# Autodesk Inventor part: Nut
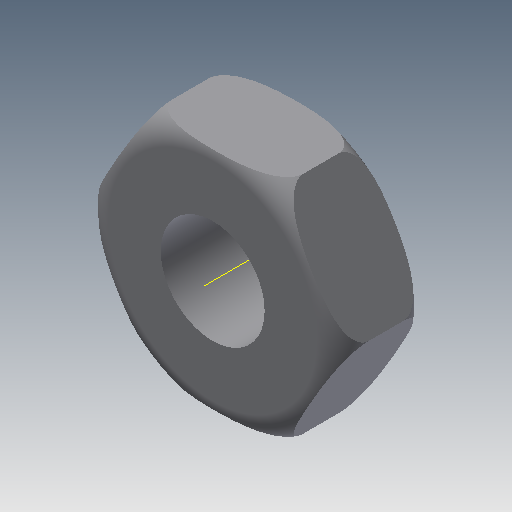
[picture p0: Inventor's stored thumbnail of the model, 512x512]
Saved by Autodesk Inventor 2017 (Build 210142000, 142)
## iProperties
Created: 2009-04
Part Number: Nut
Document SubType Name: Modeling
Designer: Sham
Density: 1 g/cm^3
Material: Generic
Appearance: Default
Mass: 4.65064 g
Surface Area: 21.3319 cm^2
Volume: 4.65064 cm^3
Author: Sham
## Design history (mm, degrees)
sketch "Sketch1"
  geometry: L1 (7.5, 12.99)-(15, 0); L2 (15, 0)-(7.5, -12.99); L3 (7.5, -12.99)-(-7.5, -12.99); L4 (-7.5, -12.99)-(-15, 0); L5 (-15, 0)-(-7.5, 12.99); L6 (-7.5, 12.99)-(7.5, 12.99); C1 r 6 at (0, 0); 1 further point
  constraints: 12 end point, 1 centre point, 1 coincident, 13 other
  dimensions: "d0" = 30 distance of L1.end L4.end; "d1" = 12 diameter of C1
extrude "Extrusion1" new body sketch "Sketch1" distance "d2" = 12; taper "d3" = 0 deg
sketch "Sketch2"
  geometry: L1 (-12, 0)-(-12, -0.022); L2 (-15, 7)-(-15, 3); L3 (0, -2.87)-(0, 12.87) reference; A1 r 3 centre (-12, 7) between (-12, 10) and (-15, 7); A2 r 3 centre (-12, 3) between (-15, 3) and (-12, 0)
  constraints: 4 end point, 4 point on circle, 2 centre point, 1 tangent
revolve "Revolution1" sketch "Sketch2" stored, may be unused: angle "d7" = 90 deg
body "Solid1"
other parameters: "d6" = 90 deg
